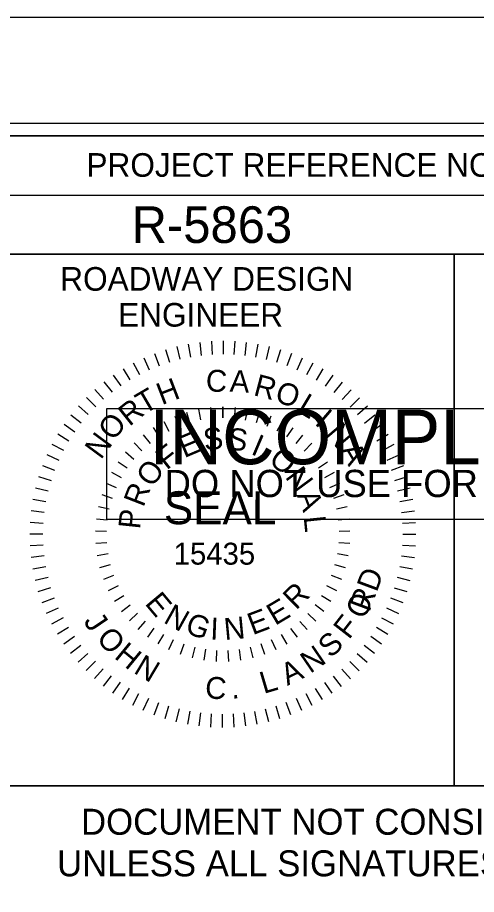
# Model space of a CAD drawing. Extents: x 557032 to 558930, y 525869 to 527437.
# Drawn here: x 558507 to 558604.2, y 526783.7 to 526969.2 of the extents above; entities that cross this region are included whole.
import ezdxf

# ---------------------------------------------------------------- set-up
doc = ezdxf.new("R2010")
doc.units = 0
for name, color, linetype in [('Old_Level_21', 7, 'Continuous'), ('Sheet Cutting Line CELL', 7, 'Continuous'), ('Sheet Data Field CELL', 7, 'Continuous'), ('Sheet Plot Border Inside CELL', 7, 'Continuous'), ('Sheet Plot Border Outside CELL', 7, 'Continuous'), ('Sheet Profile CELL', 7, 'Continuous'), ('Sheet Profile Grid Major CELL', 7, 'Continuous'), ('Sheet Sticker Exception Certification CELL', 7, 'Continuous'), ('Sheet Sticker Incomplete CELL', 7, 'Continuous')]:
    doc.layers.add(name, color=color, linetype=linetype)

msp = doc.modelspace()

# ---------------------------------------------------------------- linework, layer by layer
at = {"layer": 'Old_Level_21'}
for p, q in [((558545.61, 526900.5), (558545.94, 526897.74)), ((558548.07, 526900.72), (558548.23, 526897.94)), ((558550.54, 526900.8), (558550.53, 526898.01)), ((558553, 526900.72), (558552.83, 526897.94)), ((558555.46, 526900.49), (558555.13, 526897.73)), ((558538.37, 526898.96), (558539.2, 526896.3)), ((558540.75, 526899.62), (558541.41, 526896.92)), ((558543.17, 526900.14), (558543.66, 526897.4)), ((558557.9, 526900.12), (558557.4, 526897.38)), ((558560.31, 526899.6), (558559.65, 526896.89)), ((558562.7, 526898.93), (558561.86, 526896.27)), ((558533.76, 526897.22), (558534.89, 526894.68)), ((558536.04, 526898.16), (558537.02, 526895.55)), ((558565.03, 526898.12), (558564.03, 526895.52)), ((558567.3, 526897.17), (558566.16, 526894.63)), ((558529.38, 526894.93), (558530.82, 526892.55)), ((558531.53, 526896.14), (558532.82, 526893.67)), ((558569.53, 526896.09), (558568.23, 526893.62)), ((558571.68, 526894.87), (558570.23, 526892.49)), ((558527.3, 526893.59), (558528.88, 526891.3)), ((558573.75, 526893.53), (558572.16, 526891.24)), ((558525.32, 526892.13), (558527.03, 526889.94)), ((558575.73, 526892.06), (558574.01, 526889.87)), ((558523.41, 526890.55), (558525.26, 526888.47)), ((558577.63, 526890.48), (558575.78, 526888.4)), ((558521.62, 526888.86), (558523.58, 526886.89)), ((558579.42, 526888.78), (558577.45, 526886.82)), ((558519.92, 526887.07), (558522, 526885.22)), ((558542.81, 526885.75), (558543.47, 526883.52)), ((558545.34, 526886.37), (558545.78, 526884.09)), ((558547.91, 526886.74), (558548.14, 526884.43)), ((558550.52, 526886.86), (558550.51, 526884.54)), ((558550.51, 526884.54), (558550.52, 526886.86)), ((558553.12, 526886.73), (558552.89, 526884.42)), ((558555.69, 526886.35), (558555.24, 526884.07)), ((558558.22, 526885.73), (558557.55, 526883.5)), ((558581.11, 526886.98), (558579.03, 526885.14)), ((558518.34, 526885.17), (558520.53, 526883.45)), ((558537.99, 526883.79), (558539.07, 526881.73)), ((558540.35, 526884.89), (558541.23, 526882.73)), ((558560.67, 526884.86), (558559.8, 526882.71)), ((558563.03, 526883.76), (558561.95, 526881.7)), ((558582.69, 526885.08), (558580.5, 526883.37)), ((558516.87, 526883.19), (558519.16, 526881.6)), ((558535.75, 526882.48), (558537.01, 526880.53)), ((558565.28, 526882.44), (558564, 526880.49)), ((558584.15, 526883.09), (558581.86, 526881.51)), ((558515.53, 526881.12), (558517.91, 526879.67)), ((558533.64, 526880.95), (558535.09, 526879.13)), ((558567.38, 526880.9), (558565.92, 526879.09)), ((558585.49, 526881.02), (558583.1, 526879.58)), ((558514.31, 526878.97), (558516.78, 526877.67)), ((558531.69, 526879.22), (558533.31, 526877.56)), ((558569.32, 526879.17), (558567.7, 526877.51)), ((558586.7, 526878.87), (558584.23, 526877.57)), ((558513.23, 526876.75), (558515.77, 526875.6)), ((558529.91, 526877.32), (558531.68, 526875.82)), ((558571.09, 526877.26), (558569.32, 526875.77)), ((558587.77, 526876.64), (558585.23, 526875.51)), ((558512.28, 526874.47), (558514.88, 526873.47)), ((558528.33, 526875.26), (558530.24, 526873.93)), ((558572.67, 526875.19), (558570.76, 526873.87)), ((558588.72, 526874.36), (558586.11, 526873.37)), ((558526.95, 526873.05), (558528.98, 526871.91)), ((558574.04, 526872.98), (558572.01, 526871.85)), ((558511.47, 526872.14), (558514.13, 526871.3)), ((558525.79, 526870.71), (558527.92, 526869.78)), ((558575.19, 526870.64), (558573.06, 526869.72)), ((558589.52, 526872.03), (558586.86, 526871.2)), ((558510.8, 526869.75), (558513.51, 526869.09)), ((558590.18, 526869.64), (558587.48, 526868.99)), ((558510.28, 526867.34), (558513.02, 526866.84)), ((558524.87, 526868.28), (558527.08, 526867.56)), ((558576.11, 526868.21), (558573.9, 526867.5)), ((558590.7, 526867.23), (558587.96, 526866.73)), ((558524.18, 526865.77), (558526.45, 526865.27)), ((558576.79, 526865.7), (558574.53, 526865.2)), ((558509.91, 526864.9), (558512.67, 526864.57)), ((558523.74, 526863.2), (558526.04, 526862.92)), ((558591.06, 526864.79), (558588.3, 526864.46)), ((558509.68, 526862.45), (558512.46, 526862.28)), ((558577.23, 526863.13), (558574.92, 526862.86)), ((558591.28, 526862.33), (558588.5, 526862.17)), ((558509.6, 526859.98), (558512.39, 526859.97)), ((558523.55, 526860.61), (558525.87, 526860.55)), ((558577.41, 526860.53), (558575.09, 526860.48)), ((558591.36, 526859.86), (558588.57, 526859.87)), ((558509.67, 526857.51), (558512.45, 526857.67)), ((558523.61, 526858.01), (558525.92, 526858.17)), ((558577.35, 526857.93), (558575.03, 526858.1)), ((558523.92, 526855.42), (558526.2, 526855.81)), ((558574.75, 526855.82), (558577.04, 526855.43)), ((558591.28, 526857.39), (558588.5, 526857.56)), ((558509.9, 526855.05), (558512.66, 526855.38)), ((558591.05, 526854.94), (558588.29, 526855.27)), ((558510.26, 526852.61), (558513, 526853.1)), ((558524.47, 526852.88), (558526.71, 526853.48)), ((558576.46, 526852.8), (558574.23, 526853.42)), ((558590.68, 526852.5), (558587.94, 526853)), ((558510.78, 526850.19), (558513.48, 526850.85)), ((558525.28, 526850.4), (558527.45, 526851.22)), ((558575.66, 526850.33), (558573.49, 526851.15)), ((558590.16, 526850.08), (558587.45, 526850.75)), ((558511.43, 526847.81), (558514.1, 526848.64)), ((558526.31, 526848.01), (558528.39, 526849.04)), ((558574.61, 526847.95), (558572.53, 526848.98)), ((558589.49, 526847.7), (558586.83, 526848.53)), ((558527.57, 526845.74), (558529.55, 526846.96)), ((558573.35, 526845.67), (558571.37, 526846.9)), ((558512.24, 526845.48), (558514.85, 526846.46)), ((558529.05, 526843.59), (558530.9, 526845)), ((558571.86, 526843.53), (558570.02, 526844.94)), ((558588.68, 526845.37), (558586.07, 526846.37)), ((558513.18, 526843.2), (558515.72, 526844.33)), ((558530.73, 526841.6), (558532.43, 526843.18)), ((558570.18, 526841.55), (558568.48, 526843.13)), ((558587.73, 526843.09), (558585.19, 526844.24)), ((558514.26, 526840.97), (558516.73, 526842.27)), ((558532.58, 526839.78), (558534.13, 526841.52)), ((558568.32, 526839.73), (558566.78, 526841.47)), ((558586.65, 526840.87), (558584.18, 526842.17)), ((558515.47, 526838.82), (558517.85, 526840.26)), ((558534.61, 526838.15), (558535.98, 526840.02)), ((558566.28, 526838.1), (558564.92, 526839.98)), ((558585.43, 526838.72), (558583.05, 526840.17)), ((558516.81, 526836.75), (558519.1, 526838.32)), ((558536.79, 526836.72), (558537.97, 526838.72)), ((558539.09, 526835.51), (558540.07, 526837.61)), ((558561.8, 526835.47), (558560.82, 526837.58)), ((558564.11, 526836.68), (558562.93, 526838.68)), ((558584.09, 526836.65), (558581.8, 526838.24)), ((558518.27, 526834.76), (558520.46, 526836.47)), ((558541.5, 526834.52), (558542.28, 526836.71)), ((558544.54, 526836.03), (558543.98, 526833.77)), ((558546.55, 526833.27), (558546.89, 526835.56)), ((558554.33, 526833.26), (558554, 526835.55)), ((558556.89, 526833.75), (558556.33, 526836.01)), ((558559.38, 526834.49), (558558.61, 526836.69)), ((558582.62, 526834.67), (558580.43, 526836.39)), ((558519.85, 526832.86), (558521.93, 526834.7)), ((558549.14, 526833.01), (558549.25, 526835.33)), ((558551.74, 526833.01), (558551.64, 526835.33)), ((558581.04, 526832.77), (558578.96, 526834.62)), ((558521.54, 526831.06), (558523.51, 526833.02)), ((558579.34, 526830.98), (558577.38, 526832.95)), ((558523.33, 526829.36), (558525.18, 526831.44)), ((558525.23, 526827.78), (558526.95, 526829.97)), ((558575.64, 526827.71), (558573.93, 526829.9)), ((558577.54, 526829.29), (558575.7, 526831.37)), ((558527.21, 526826.31), (558528.8, 526828.6)), ((558573.65, 526826.25), (558572.07, 526828.54)), ((558529.28, 526824.97), (558530.73, 526827.35)), ((558531.43, 526823.75), (558532.73, 526826.22)), ((558569.42, 526823.7), (558568.13, 526826.17)), ((558571.58, 526824.91), (558570.14, 526827.29)), ((558533.65, 526822.67), (558534.8, 526825.21)), ((558535.93, 526821.72), (558536.92, 526824.32)), ((558564.92, 526821.68), (558563.93, 526824.29)), ((558567.2, 526822.62), (558566.06, 526825.16)), ((558538.26, 526820.91), (558539.09, 526823.57)), ((558540.64, 526820.24), (558541.31, 526822.95)), ((558543.05, 526819.72), (558543.56, 526822.46)), ((558557.79, 526819.7), (558557.29, 526822.44)), ((558560.2, 526820.22), (558559.55, 526822.92)), ((558562.59, 526820.87), (558561.76, 526823.54)), ((558545.49, 526819.35), (558545.83, 526822.11)), ((558547.95, 526819.12), (558548.12, 526821.9)), ((558550.42, 526819.04), (558550.43, 526821.83)), ((558552.89, 526819.11), (558552.73, 526821.9)), ((558555.35, 526819.34), (558555.02, 526822.1))]:
    msp.add_line(p, q, dxfattribs=at)
at = {"layer": 'Sheet Cutting Line CELL'}
msp.add_line((558716.45, 526969.22), (557032.45, 526969.22), dxfattribs=at)
at = {"layer": 'Sheet Plot Border Inside CELL'}
msp.add_lwpolyline([(557045.45, 525891.67), (558711.95, 525891.67), (558711.95, 526946.77), (557045.45, 526946.77)], close=True, dxfattribs=at)
at = {"layer": 'Sheet Plot Border Outside CELL'}
msp.add_lwpolyline([(557032.45, 525869.22), (558716.45, 525869.22), (558716.45, 526969.22), (557032.45, 526969.22)], close=True, dxfattribs=at)
at = {"layer": 'Sheet Profile CELL'}
for p, q in [((558499.4, 526931.67), (558699.45, 526931.67)), ((558599.45, 526919.17), (558599.45, 526806.72))]:
    msp.add_line(p, q, dxfattribs=at)
for points in [[(558699.45, 526944.22), (557199.45, 526944.22), (557199.45, 525894.22), (558699.45, 525894.22)], [(558499.4, 526944.22), (558699.45, 526944.22), (558699.45, 526919.17), (558499.4, 526919.17)], [(558499.4, 526919.17), (558599.45, 526919.17), (558599.45, 526806.67), (558499.4, 526806.67)], [(558599.45, 526919.17), (558699.45, 526919.17), (558699.45, 526806.67), (558599.45, 526806.67)]]:
    msp.add_lwpolyline(points, close=True, dxfattribs=at)
at = {"layer": 'Sheet Profile Grid Major CELL'}
msp.add_lwpolyline([(558249.45, 526444.22), (558299.45, 526444.22), (558299.45, 526944.22), (558349.45, 526944.22), (558349.45, 526444.22), (558399.45, 526444.22), (558399.45, 526944.22), (558449.45, 526944.22), (558449.45, 526444.22), (558499.45, 526444.22), (558499.45, 526944.22), (558525.75, 526944.22)], dxfattribs=at)
at = {"layer": 'Sheet Sticker Exception Certification CELL'}
msp.add_line((558499.4, 526806.67), (558699.44, 526806.67), dxfattribs=at)
msp.add_line((558499.4, 526806.67), (558699.44, 526806.67), dxfattribs=at)
at = {"layer": 'Sheet Sticker Incomplete CELL'}
msp.add_lwpolyline([(558525.97, 526863.02), (558525.97, 526886.52), (558672.97, 526886.52), (558672.97, 526863.02)], close=True, dxfattribs=at)

# ---------------------------------------------------------------- texts
at = {"layer": 'Old_Level_21'}
for s, height, rotation, p in [('C', 4.64, 357.2771, (558546.81, 526890.16)), ('H', 4.64, 20.9878, (558537.57, 526887.19)), ('A', 4.64, 357.2771, (558551.88, 526890.06)), ('R', 4.64, 345.2678, (558556.79, 526889.37)), ('T', 4.64, 30.4198, (558533.83, 526885.18)), ('O', 4.64, 342.211, (558561.29, 526888.03)), ('L', 4.64, 329.0747, (558566.01, 526885.96)), ('R', 4.64, 38.5807, (558530.71, 526882.59)), ('I', 4.64, 319.4993, (558569.74, 526883.26)), ('O', 4.64, 51.6375, (558527.34, 526879.47)), ('N', 4.64, 310.2048, (558572.07, 526881.07)), ('S', 4.64, 7.5683, (558546.68, 526877.57)), ('S', 4.64, 352.272, (558551.31, 526877.95)), ('N', 4.64, 53.5969, (558524.67, 526875.55)), ('E', 4.64, 22.8645, (558542.32, 526875.98)), ('I', 4.64, 336.9758, (558556.24, 526876.94)), ('F', 4.64, 38.1608, (558538.6, 526873.36)), ('A', 4.64, 300.4373, (558575.12, 526877.64)), ('O', 4.64, 321.6795, (558559.98, 526875.13)), ('O', 4.64, 53.457, (558535.51, 526869.62)), ('N', 4.64, 306.3833, (558563.55, 526872.01)), ('R', 4.64, 68.7533, (558533.67, 526865.46)), ('SEAL', 6.965, 359.9202, (558538, 526862.03)), ('A', 4.64, 291.0871, (558566.09, 526868.21)), ('P', 4.64, 84.0495, (558532.96, 526860.86)), ('L', 4.64, 275.7908, (558567.59, 526863.61)), ('15435', 4.64, 359.9202, (558540.08, 526853.49)), (' RD', 4.64, 69.5926, (558580.9, 526841.68)), ('R', 4.64, 44.4851, (558566, 526843.73)), ('E', 4.64, 309.9903, (558533.83, 526845.21)), ('O ', 4.64, 60.9198, (558580.23, 526841.66)), ('N', 4.64, 330.8453, (558537.72, 526841.33)), ('E', 4.64, 30.714, (558561.57, 526840.5)), ('J', 4.64, 303.8552, (558520.88, 526841.43)), ('G', 4.64, 339.6116, (558542.26, 526839.15)), ('E', 4.64, 20.7281, (558556.81, 526838.53)), ('F', 4.64, 52.1272, (558577.2, 526837.47)), ('I', 4.64, 357.7064, (558547.78, 526837.66)), ('N', 4.64, 5.336, (558550.93, 526837.5)), ('O', 4.64, 311.927, (558523.53, 526837.73)), ('S', 4.64, 43.2446, (558573.33, 526833.54)), ('H', 4.64, 320.5697, (558527.31, 526833.82)), ('N', 4.64, 34.362, (558568.99, 526830.33)), ('N', 4.64, 329.2423, (558531.41, 526830.68)), ('A', 4.64, 25.5393, (558564.16, 526827.81)), ('C', 4.64, 356.0101, (558546.63, 526825.23)), ('L', 4.64, 16.5368, (558559.14, 526826.11)), ('.', 4.64, 3.7525, (558552.39, 526825.1))]:
    msp.add_text(s, height=height, rotation=rotation, dxfattribs=at).set_placement(p)
at = {"layer": 'Sheet Data Field CELL'}
msp.add_text('R-5863   ', height=7.75, dxfattribs=at).set_placement((558531.18, 526921.53))
at = {"layer": 'Sheet Profile CELL'}
for s, height, p in [('PROJECT REFERENCE NO.', 5.0001, (558521.62, 526935.53)), ('ROADWAY DESIGN', 5.0001, (558516.07, 526911.43)), ('ENGINEER', 5, (558528.32, 526903.83))]:
    msp.add_text(s, height=height, dxfattribs=at).set_placement(p)
at = {"layer": 'Sheet Sticker Exception Certification CELL'}
for s, p in [('DOCUMENT NOT CONSIDERED FINAL', (558520.47, 526796.33)), ('DOCUMENT NOT CONSIDERED FINAL', (558520.47, 526796.33)), ('UNLESS ALL SIGNATURES COMPLETED', (558515.4, 526787.53)), ('UNLESS ALL SIGNATURES COMPLETED', (558515.4, 526787.53))]:
    msp.add_text(s, height=5.5, dxfattribs=at).set_placement(p)
at = {"layer": 'Sheet Sticker Incomplete CELL'}
for s, height, p in [('INCOMPLETE PLANS', 11.52, (558534.92, 526874.72)), ('DO NOT USE FOR R/W ACQUISITION', 5.76, (558538.17, 526867.77))]:
    msp.add_text(s, height=height, dxfattribs=at).set_placement(p)

doc.saveas('drawing.dxf')
